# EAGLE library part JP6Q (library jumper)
JUMPER
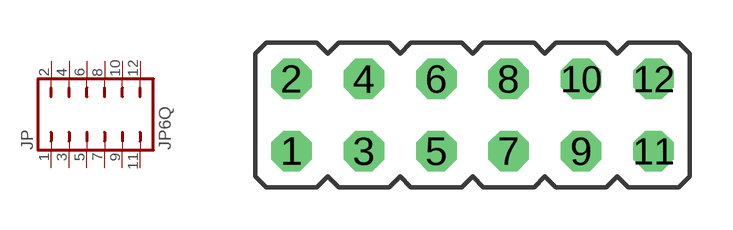
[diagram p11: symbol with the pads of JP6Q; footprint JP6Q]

Designator prefix JP

## JP6Q  [JP6Q]
1  1  pas
2  2  pas
3  3  pas
4  4  pas
5  5  pas
6  6  pas
7  7  pas
8  8  pas
9  9  pas
10  10  pas
11  11  pas
12  12  pas

## Footprint JP6Q (pad centres in mm)
JUMPER
drill 0.914 octagon: 1 -6.35,-1.27; 2 -6.35,1.27; 3 -3.81,-1.27; 4 -3.81,1.27; 5 -1.27,-1.27; 6 -1.27,1.27; 7 1.27,-1.27; 8 1.27,1.27; 9 3.81,-1.27; 10 3.81,1.27; 11 6.35,-1.27; 12 6.35,1.27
